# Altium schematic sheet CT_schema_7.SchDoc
size 254 x 245 mm
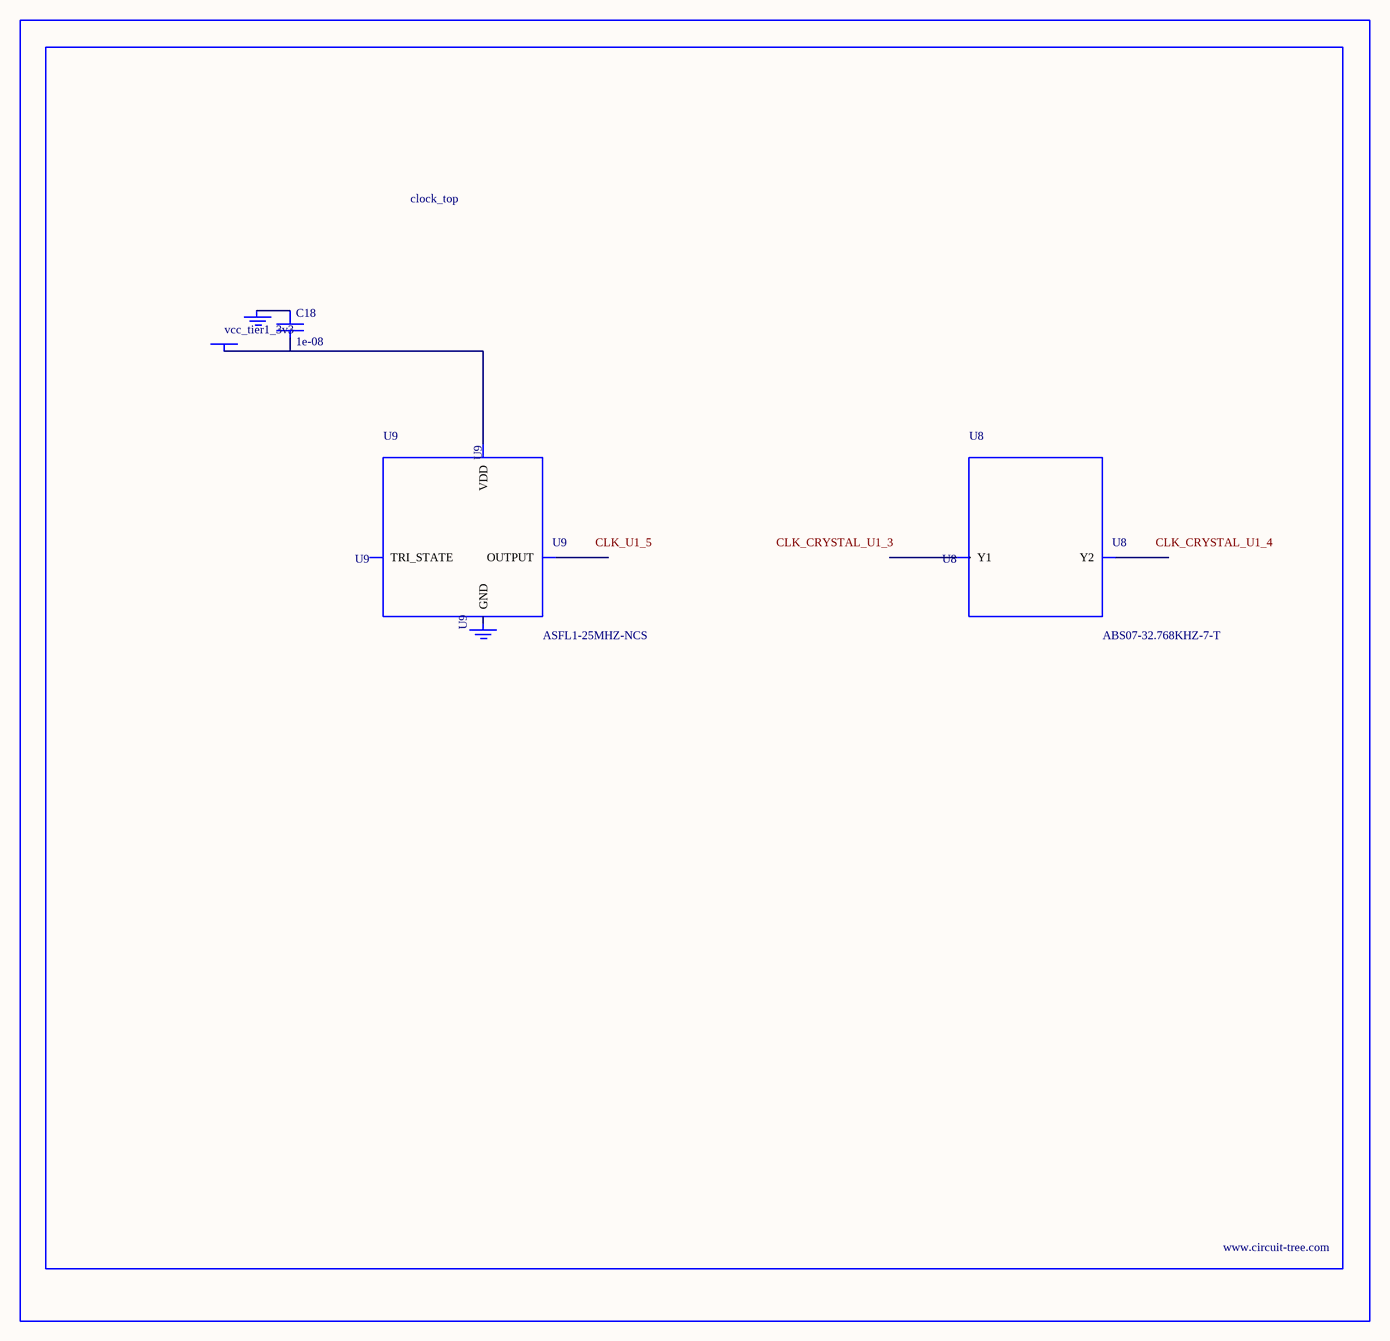
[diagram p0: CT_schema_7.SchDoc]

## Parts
BORDER6  (no value)
C18  1e-08  [C0402]
GND_INSTANCE_6_0  (no value)
GND_INSTANCE_6_1  (no value)
POWER_INSTANCE_6_0  vcc_tier1_3v3
U8  ABS07-32.768KHZ-7-T  [ABS07-32.768KHZ-7-T]
U9  ASFL1-25MHZ-NCS  [ASFL1]

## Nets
NetC18_1: C18.1 GND_INSTANCE_6_0.0(GND)
NetC18_2: C18.2 POWER_INSTANCE_6_0.0(PWR) U9.4(VDD)

Not connected (* = marked no-connect by the designer): GND_INSTANCE_6_1 0(GND); U8 1(Y1) 2(Y2); U9 1(TRI_STATE) 2(GND) 3(OUTPUT)

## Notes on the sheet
- Labels drawn without touching a wire or pin: CLK_CRYSTAL_U1_3, CLK_CRYSTAL_U1_4, CLK_U1_5

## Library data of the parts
BORDER6 = BORDER_PAGE6
C18 = C0402C103K3RAC
GND_INSTANCE_6_0 GND_INSTANCE_6_1 = GND
POWER_INSTANCE_6_0 = PWR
